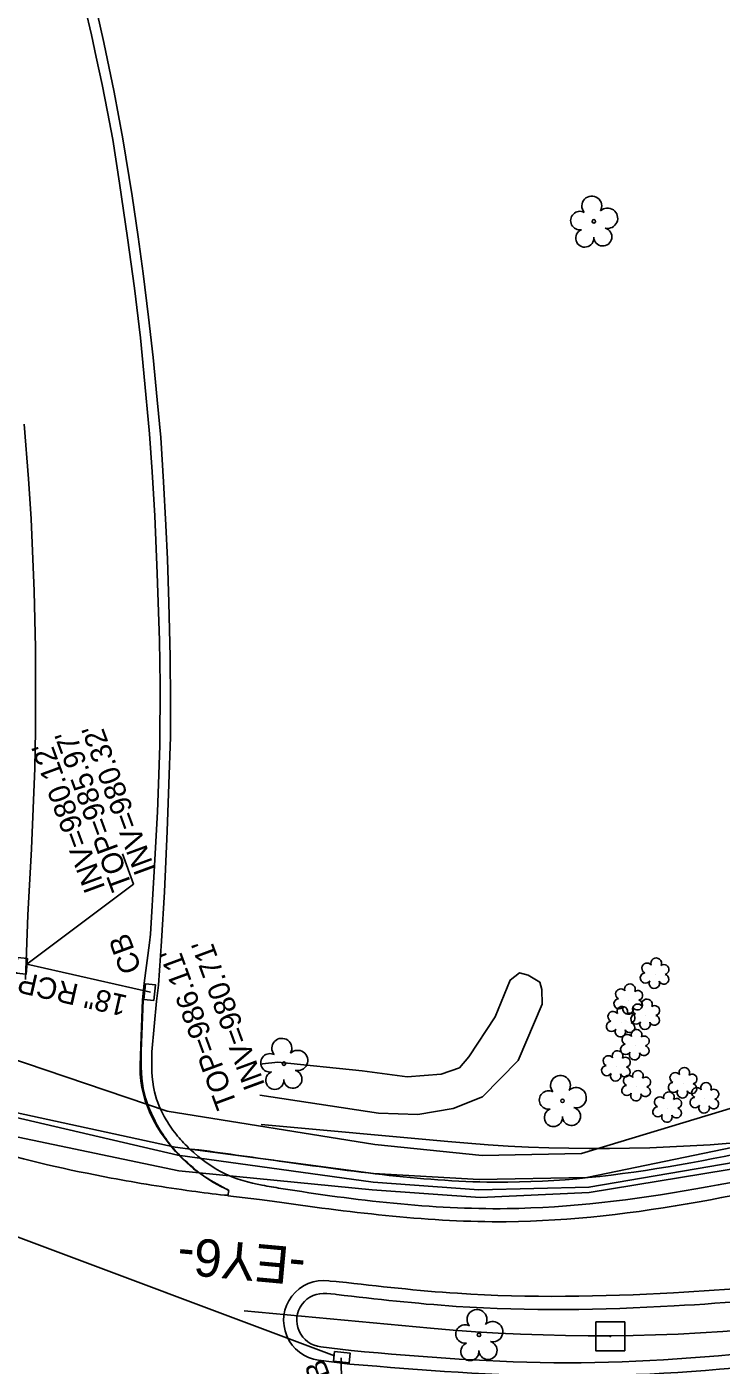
# Model space of a CAD drawing. Extents: x 1614427 to 1617186, y 896524 to 905462.
# Drawn here: x 1615875.6 to 1616005.3, y 904028.5 to 904278.6 of the extents above; entities that cross this region are included whole.
import ezdxf

# ---------------------------------------------------------------- set-up
doc = ezdxf.new("R2010")
doc.units = 0
for name, color, linetype in [('Exist Horizontal Alignment', 7, 'Continuous'), ('Exist Horizontal Alignment Direction Label', 7, 'Continuous'), ('Exist Right of Way Line', 7, 'Continuous'), ('Exist Roads Curbs', 7, 'Continuous'), ('Exist Roads EOP', 7, 'Continuous'), ('Exist Roads EOP Other', 7, 'Continuous'), ('Exist Roads EOT', 7, 'Continuous'), ('Exist Structure Minor Catch Basin', 7, 'Continuous'), ('Exist Structure Minor Catch Basin Leader', 7, 'Continuous'), ('Exist Structure Minor Catch Basin Text', 7, 'Continuous'), ('Exist Structure Minor Catch Basin Top Elevation', 7, 'Continuous'), ('Exist Structure Minor Pipes RCP 15 Inch', 7, 'Continuous'), ('Exist Structure Minor Pipes RCP 18 Inch', 7, 'Continuous'), ('Exist Structure Minor Pipes RCP 18 Inch Invert', 7, 'Continuous'), ('Exist Structure Minor Pipes RCP 18 Inch Text', 7, 'Continuous'), ('Exist Utilities Gas UG Line SUE LOS B', 7, 'Continuous'), ('Exist Utilities Other Pole With Base CELL', 7, 'Continuous'), ('Exist Utilities Power UG Cable SUE LOS B', 7, 'Continuous'), ('Exist Utilities Telephone UG FO SUE LOS B', 7, 'Continuous'), ('Exist Utilities Water UG Line SUE LOS B', 7, 'Continuous'), ('Exist Vegetation Hedge Row', 7, 'Continuous'), ('Exist Vegetation Shrub CELL', 7, 'Continuous'), ('Exist Vegetation Tree CELL', 7, 'Continuous')]:
    doc.layers.add(name, color=color, linetype=linetype)

msp = doc.modelspace()

# ---------------------------------------------------------------- linework, layer by layer
at = {"layer": 'Exist Horizontal Alignment'}
msp.add_line((1615916.17, 904038.64), (1615951, 904035.43), dxfattribs=at)
msp.add_arc((1615982.39, 904376.05), 342.06, 264.7333, 287.2667, dxfattribs=at)
at = {"layer": 'Exist Right of Way Line'}
msp.add_line((1615919.38, 904073.49), (1615954.21, 904070.28), dxfattribs=at)
msp.add_arc((1615982.39, 904376.05), 307.06, 264.7333, 287.2667, dxfattribs=at)
at = {"layer": 'Exist Roads Curbs'}
for p, q in [((1615898.96, 904087.08), (1615899.79, 904096.52)), ((1615933.17, 904041.78), (1615933.45, 904041.7)), ((1615936.16, 904031.22), (1615930.53, 904031.95))]:
    msp.add_line(p, q, dxfattribs=at)
for points in [[(1615893.5, 904257.65), (1615891.93, 904266.36), (1615889.96, 904275.68), (1615887.58, 904286.27), (1615885.87, 904293.7), (1615885.64, 904294.86), (1615885.5, 904296.02), (1615885.43, 904297.19), (1615885.44, 904298.37), (1615885.53, 904299.54), (1615885.57, 904299.9), (1615885.81, 904300.71), (1615886.13, 904301.49), (1615886.52, 904302.24), (1615886.98, 904302.96), (1615887.5, 904303.62), (1615887.72, 904303.86), (1615888.36, 904304.53), (1615889.06, 904305.14), (1615889.8, 904305.68), (1615890.59, 904306.16), (1615891.42, 904306.57), (1615892.28, 904306.9), (1615893.01, 904307.12)], [(1615899.79, 904096.52), (1615900.18, 904099.49), (1615900.77, 904107.74), (1615901.33, 904116.93), (1615901.83, 904128.29), (1615902.14, 904137.09), (1615902.4, 904145.94), (1615902.44, 904152.54), (1615902.38, 904160.85), (1615902.1, 904171.04), (1615901.84, 904179.09), (1615901.55, 904185.49), (1615901.14, 904193.58), (1615900.6, 904201.84), (1615899.96, 904208.86), (1615899.17, 904216.8), (1615898.31, 904224.32), (1615897.3, 904232.49), (1615896.4, 904239.36), (1615895.25, 904247.03), (1615893.5, 904257.65)], [(1615931.63, 904041.88), (1615932.4, 904041.81), (1615933.17, 904041.78)]]:
    msp.add_lwpolyline(points, dxfattribs=at)
msp.add_ellipse((1615930.99, 904036.92), major_axis=(-2.73, -4.18), ratio=0.999289, start_param=3.591477, end_param=6.769643, dxfattribs=at)
for points in [[(1616117.5, 904141.64), (1616119.61, 904131.89), (1616118.86, 904120.99), (1616117.54, 904115.53), (1616115.97, 904111.79), (1616113.21, 904107), (1616110.89, 904103.69), (1616104.9, 904097.71), (1616096.36, 904092.38), (1616065.87, 904079.76), (1616033.72, 904069.07), (1616000.54, 904061.43), (1615965.3, 904057.76), (1615923.02, 904061.54), (1615919.54, 904062.14), (1615912.5, 904064.32), (1615906.06, 904068.89), (1615903.75, 904071.29), (1615901.6, 904074.35), (1615899.43, 904079.59), (1615898.96, 904087.08)], [(1615933.45, 904041.7), (1615955.8, 904039.5), (1615996.5, 904039.58), (1616026.82, 904042.27), (1616053.3, 904046.56), (1616074.92, 904051.74), (1616097, 904058.32)], [(1616097.28, 904047.76), (1616058.24, 904037.32), (1616017.59, 904031.47), (1615976.53, 904028.93), (1615936.16, 904031.22)]]:
    msp.add_spline(points, degree=3, dxfattribs=at)
at = {"layer": 'Exist Roads EOP'}
for p, q in [((1615896.95, 904087.21), (1615897.3, 904096.73)), ((1615913.16, 904060.17), (1615913.33, 904061.16)), ((1615919.06, 904059.46), (1615913.16, 904060.17)), ((1615933.35, 904044.14), (1615933.92, 904044.1)), ((1615935.89, 904028.72), (1615930.08, 904029.44))]:
    msp.add_line(p, q, dxfattribs=at)
msp.add_lwpolyline([(1615931.99, 904044.27), (1615932.27, 904044.23), (1615933.35, 904044.14)], dxfattribs=at)
msp.add_ellipse((1615931.03, 904036.86), major_axis=(-4.43, -6.02), ratio=0.998974, start_param=3.648024, end_param=6.790921, dxfattribs=at)
for points in [[(1616119.62, 904142.34), (1616122.11, 904132.17), (1616121.32, 904120.53), (1616119.78, 904114.71), (1616118.22, 904110.85), (1616115.45, 904105.64), (1616112.79, 904102.18), (1616106.49, 904095.88), (1616097.4, 904090.23), (1616066.74, 904077.37), (1616034.38, 904066.74), (1616001.17, 904059.04), (1615965.14, 904055.31), (1615922.78, 904058.94), (1615919.06, 904059.46)], [(1615913.33, 904061.16), (1615908.86, 904063.71), (1615904.56, 904067.32), (1615902.11, 904070.03), (1615899.96, 904073.38), (1615897.55, 904079.2), (1615896.95, 904087.21)], [(1615933.92, 904044.1), (1615956.01, 904041.93), (1615996.4, 904042.04), (1616026.66, 904044.72), (1616052.83, 904049.09), (1616074.4, 904054.13), (1616095.78, 904060.53)], [(1616097.99, 904045.33), (1616058.52, 904034.87), (1616017.88, 904028.96), (1615976.43, 904026.45), (1615935.89, 904028.72)]]:
    msp.add_spline(points, degree=3, dxfattribs=at)
at = {"layer": 'Exist Roads EOP Other'}
msp.add_line((1615907.72, 904068.75), (1615906.28, 904068.84), dxfattribs=at)
for points in [[(1615891.63, 904257.51), (1615890.68, 904262.67), (1615889.66, 904267.81), (1615888.57, 904272.93), (1615887.64, 904277.08), (1615885.33, 904287.12)], [(1615913.18, 904061.27), (1615911.81, 904061.92), (1615910.48, 904062.64), (1615909.2, 904063.43), (1615907.95, 904064.29), (1615906.75, 904065.21), (1615906.68, 904065.27), (1615905.51, 904066.27), (1615904.4, 904067.33), (1615903.35, 904068.45), (1615902.35, 904069.62), (1615901.42, 904070.83), (1615900.71, 904071.86), (1615899.96, 904073.06), (1615899.27, 904074.29), (1615898.65, 904075.56), (1615898.1, 904076.86), (1615897.71, 904077.93), (1615897.36, 904079.14), (1615897.09, 904080.36), (1615896.89, 904081.61), (1615896.78, 904082.86), (1615896.74, 904084.11), (1615896.75, 904084.47), (1615896.92, 904089.91), (1615897.2, 904096.76), (1615897.48, 904099.9), (1615898.5, 904107.41), (1615898.67, 904109.06), (1615899.37, 904120.77), (1615900, 904131.92), (1615900.17, 904137.07), (1615900.43, 904144.27), (1615900.52, 904155.67), (1615900.38, 904163.91), (1615899.94, 904176.46), (1615899.48, 904187.22), (1615899.03, 904195.42), (1615898.52, 904202.52), (1615897.47, 904213.87), (1615896.81, 904220.44), (1615895.69, 904229.74), (1615894.41, 904239.18), (1615892.92, 904249.38), (1615891.63, 904257.51)], [(1615875.35, 904100.57), (1615875.75, 904112.62), (1615876.44, 904124.97), (1615877.08, 904140.06), (1615877.24, 904147.11), (1615877.21, 904162.52), (1615876.98, 904173.16), (1615876.39, 904186.64), (1615875.93, 904194.1), (1615875.09, 904204.35)]]:
    msp.add_lwpolyline(points, dxfattribs=at)
msp.add_spline([(1616106.96, 904106.8), (1616101.73, 904101.46), (1616094.3, 904096.91), (1616063.81, 904084.29), (1616032.43, 904073.94), (1615999.62, 904066.32), (1615965.45, 904062.7), (1615923.72, 904066.51), (1615907.72, 904068.75)], degree=3, dxfattribs=at)
at = {"layer": 'Exist Roads EOT'}
msp.add_line((1615912.51, 904060.26), (1615913.08, 904060.29), dxfattribs=at)
msp.add_ellipse((1615972.71, 904454.31), major_axis=(399.48, 187.91), ratio=0.997263, start_param=4.002237, end_param=4.130845, dxfattribs=at)
msp.add_spline([(1615844.2, 904077.02), (1615867.65, 904069.04), (1615891.35, 904063.48), (1615906.39, 904061.04), (1615912.51, 904060.26)], degree=3, dxfattribs=at)
at = {"layer": 'Exist Structure Minor Catch Basin'}
for points in [[(1615873.86, 904104.68), (1615875.71, 904104.51), (1615875.46, 904101.54), (1615873.67, 904101.75), (1615873.86, 904104.68)], [(1615899.3, 904096.67), (1615897.47, 904096.83), (1615897.76, 904099.79), (1615899.63, 904099.56), (1615899.3, 904096.67)], [(1615933.06, 904031.04), (1615932.86, 904029.28), (1615935.81, 904028.92), (1615936.01, 904030.72), (1615933.06, 904031.04)]]:
    msp.add_lwpolyline(points, dxfattribs=at)
at = {"layer": 'Exist Structure Minor Catch Basin Leader'}
for points in [[(1615875.61, 904103.46), (1615895.54, 904118.41), (1615893.47, 904124.04)], [(1615934.33, 904029.89), (1615934.75, 903996.19), (1615936.83, 903990.56)]]:
    msp.add_lwpolyline(points, dxfattribs=at)
at = {"layer": 'Exist Structure Minor Pipes RCP 15 Inch'}
msp.add_line((1615933.05, 904030.25), (1615731.82, 904105.72), dxfattribs=at)
msp.add_line((1615933.05, 904030.25), (1615731.82, 904105.72), dxfattribs=at)
at = {"layer": 'Exist Structure Minor Pipes RCP 18 Inch'}
msp.add_line((1615898.71, 904098.2), (1615875.61, 904103.46), dxfattribs=at)
msp.add_line((1615898.71, 904098.2), (1615875.61, 904103.46), dxfattribs=at)
at = {"layer": 'Exist Utilities Gas UG Line SUE LOS B'}
msp.add_lwpolyline([(1615854.58, 904082), (1615870.95, 904076.26), (1615903.3, 904069.25), (1615940.35, 904064.34), (1615960.08, 904063.22), (1615980.19, 904063.57), (1616009.39, 904069.59), (1616033.23, 904075.98), (1616065.79, 904088.71), (1616071.64, 904092.21), (1616080.09, 904108.75), (1616091.42, 904131.52), (1616096.21, 904140.27), (1616099.08, 904143.48), (1616102.9, 904146.03), (1616112.33, 904149.72)], dxfattribs=at)
at = {"layer": 'Exist Utilities Other Pole With Base CELL'}
msp.add_line((1615984.58, 904033.9), (1615984.58, 904033.9), dxfattribs=at)
msp.add_lwpolyline([(1615981.86, 904036.6), (1615987.26, 904036.6), (1615987.26, 904031.2), (1615981.86, 904031.2), (1615981.86, 904036.6)], dxfattribs=at)
msp.add_circle((1615984.58, 904033.9), 0.0707, dxfattribs=at)
at = {"layer": 'Exist Utilities Power UG Cable SUE LOS B'}
msp.add_lwpolyline([(1615850.39, 904094.27), (1615863.9, 904088.79), (1615901.78, 904075.97), (1615940.62, 904069.74), (1615960.64, 904067.69), (1615979.21, 904068.06), (1616007.56, 904076.64), (1616032.56, 904083.45), (1616059.29, 904090.87), (1616085.68, 904100.71), (1616093.61, 904105.52), (1616099.52, 904112.39), (1616102.28, 904129.68), (1616094.33, 904153), (1616085.98, 904178.59), (1616082.67, 904190.98), (1616081.58, 904203.76)], dxfattribs=at)
at = {"layer": 'Exist Utilities Telephone UG FO SUE LOS B'}
msp.add_lwpolyline([(1615856.34, 904076.83), (1615870.05, 904071.95), (1615904.01, 904064.8), (1615940.09, 904061.28), (1615960.29, 904059.81), (1615980.62, 904060.75), (1616010.57, 904065.68), (1616034.12, 904072.52), (1616066.45, 904085.29), (1616094.72, 904098.79), (1616101.16, 904102.54), (1616107.05, 904108.53), (1616109.46, 904114.97), (1616109.89, 904122.41), (1616109.17, 904135.16), (1616109.54, 904138.63), (1616110.42, 904139.78), (1616119.05, 904144.94), (1616144.14, 904158.05), (1616163.63, 904162.04), (1616171.06, 904164.3), (1616173.72, 904166.8)], dxfattribs=at)
at = {"layer": 'Exist Utilities Water UG Line SUE LOS B'}
msp.add_lwpolyline([(1615854.96, 904080.87), (1615870.68, 904075.46), (1615903.78, 904067.73), (1615940.26, 904062.7), (1615960.04, 904061.3), (1615980.56, 904061.76), (1616010.46, 904066.89), (1616033.97, 904071.93), (1616069.14, 904081.95), (1616099.73, 904091.26), (1616134.12, 904102.78), (1616151.27, 904109.12), (1616173.83, 904118)], dxfattribs=at)
at = {"layer": 'Exist Vegetation Hedge Row'}
for points in [[(1615938.23, 904083.52), (1615946.62, 904082.36), (1615953, 904082.91), (1615956.38, 904084.07), (1615958.13, 904086.09), (1615963.08, 904093.6), (1615965.84, 904100.45), (1615967.6, 904101.8), (1615969.21, 904101.4), (1615971.43, 904100.05), (1615971.79, 904098.68), (1615971.84, 904095.94), (1615967.35, 904085.46), (1615960.72, 904078.64), (1615955.21, 904076.48), (1615948.65, 904075.36), (1615941.25, 904075.57), (1615919.09, 904078.95)], [(1615919.48, 904084.71), (1615919.58, 904084.8), (1615922.48, 904085.14), (1615938.23, 904083.52)]]:
    msp.add_lwpolyline(points, dxfattribs=at)
at = {"layer": 'Exist Vegetation Shrub CELL'}
for p, q in [((1615992.92, 904101.56), (1615992.92, 904101.56)), ((1615988, 904096.73), (1615988, 904096.73)), ((1615986.58, 904092.51), (1615986.58, 904092.51)), ((1615991.17, 904093.89), (1615991.17, 904093.89)), ((1615989.24, 904088.21), (1615989.24, 904088.21)), ((1615985.7, 904084.24), (1615985.7, 904084.24)), ((1615989.48, 904080.54), (1615989.48, 904080.54)), ((1615998.16, 904081.1), (1615998.16, 904081.1)), ((1615995.27, 904076.55), (1615995.27, 904076.55)), ((1616002.21, 904078.27), (1616002.21, 904078.27))]:
    msp.add_line(p, q, dxfattribs=at)
for centre, radius, start, end in [((1615993.15, 904103.6), 0.99, 334.8391, 200.4717), ((1615991.12, 904100.85), 0.955, 95.1099, 327.9534), ((1615991.44, 904102.68), 0.968, 35.8908, 245.4216), ((1615994.56, 904100.63), 0.937, 204.9913, 73.4601), ((1615994.59, 904102.43), 0.929, 284.4567, 126.0861), ((1615988.23, 904098.77), 0.99, 334.8391, 200.4717), ((1615992.79, 904099.87), 0.984, 151.2797, 21.387), ((1615986.2, 904096.03), 0.955, 95.1099, 327.9534), ((1615986.52, 904097.86), 0.968, 35.8908, 245.4216), ((1615989.64, 904095.8), 0.937, 204.9913, 73.4601), ((1615989.68, 904097.6), 0.929, 284.4567, 126.0861), ((1615991.4, 904095.93), 0.99, 334.8391, 200.4717), ((1615985.1, 904093.64), 0.968, 35.8908, 245.4216), ((1615986.81, 904094.55), 0.99, 334.8391, 200.4717), ((1615987.88, 904095.05), 0.984, 151.2797, 21.387), ((1615988.25, 904093.38), 0.929, 284.4567, 126.0861), ((1615989.37, 904093.19), 0.955, 95.1099, 327.9534), ((1615989.69, 904095.02), 0.968, 35.8908, 245.4216), ((1615992.85, 904094.76), 0.929, 284.4567, 126.0861), ((1615984.78, 904091.81), 0.955, 95.1099, 327.9534), ((1615988.22, 904091.58), 0.937, 204.9913, 73.4601), ((1615991.05, 904092.21), 0.984, 151.2797, 21.387), ((1615992.81, 904092.96), 0.937, 204.9913, 73.4601), ((1615986.45, 904090.83), 0.984, 151.2797, 21.387), ((1615987.75, 904089.34), 0.968, 35.8908, 245.4216), ((1615989.47, 904090.25), 0.99, 334.8391, 200.4717), ((1615990.91, 904089.08), 0.929, 284.4567, 126.0861), ((1615985.93, 904086.28), 0.99, 334.8391, 200.4717), ((1615987.44, 904087.51), 0.955, 95.1099, 327.9534), ((1615989.11, 904086.53), 0.984, 151.2797, 21.387), ((1615990.87, 904087.29), 0.937, 204.9913, 73.4601), ((1615983.9, 904083.54), 0.955, 95.1099, 327.9534), ((1615984.22, 904085.37), 0.968, 35.8908, 245.4216), ((1615987.34, 904083.31), 0.937, 204.9913, 73.4601), ((1615987.37, 904085.11), 0.929, 284.4567, 126.0861), ((1615998.39, 904083.14), 0.99, 334.8391, 200.4717), ((1615985.57, 904082.56), 0.984, 151.2797, 21.387), ((1615988, 904081.67), 0.968, 35.8908, 245.4216), ((1615989.71, 904082.58), 0.99, 334.8391, 200.4717), ((1615991.16, 904081.41), 0.929, 284.4567, 126.0861), ((1615996.68, 904082.22), 0.968, 35.8908, 245.4216), ((1615999.83, 904081.97), 0.929, 284.4567, 126.0861), ((1615987.68, 904079.84), 0.955, 95.1099, 327.9534), ((1615989.35, 904078.86), 0.984, 151.2797, 21.387), ((1615991.12, 904079.61), 0.937, 204.9913, 73.4601), ((1615995.5, 904078.59), 0.99, 334.8391, 200.4717), ((1615996.36, 904080.39), 0.955, 95.1099, 327.9534), ((1615998.03, 904079.41), 0.984, 151.2797, 21.387), ((1615999.8, 904080.17), 0.937, 204.9913, 73.4601), ((1616000.73, 904079.4), 0.968, 35.8908, 245.4216), ((1616002.44, 904080.31), 0.99, 334.8391, 200.4717), ((1616003.89, 904079.14), 0.929, 284.4567, 126.0861), ((1615993.47, 904075.85), 0.955, 95.1099, 327.9534), ((1615993.79, 904077.68), 0.968, 35.8908, 245.4216), ((1615996.91, 904075.62), 0.937, 204.9913, 73.4601), ((1615996.94, 904077.42), 0.929, 284.4567, 126.0861), ((1616000.41, 904077.57), 0.955, 95.1099, 327.9534), ((1616002.09, 904076.59), 0.984, 151.2797, 21.387), ((1616003.85, 904077.34), 0.937, 204.9913, 73.4601), ((1615995.14, 904074.87), 0.984, 151.2797, 21.387)]:
    msp.add_arc(centre, radius, start, end, dxfattribs=at)
at = {"layer": 'Exist Vegetation Tree CELL'}
for p, q in [((1615981.5, 904242.23), (1615981.5, 904242.23)), ((1615923.61, 904084.85), (1615923.61, 904084.85)), ((1615975.64, 904077.89), (1615975.64, 904077.89)), ((1615960.05, 904034.17), (1615960.05, 904034.17))]:
    msp.add_line(p, q, dxfattribs=at)
for centre in [(1615981.5, 904242.23), (1615923.61, 904084.85), (1615975.64, 904077.89), (1615960.05, 904034.17)]:
    msp.add_circle(centre, 0.326, dxfattribs=at)
for centre, radius, start, end in [((1615981.11, 904245.1), 1.86, 330.1651, 219.7134), ((1615978.89, 904242.38), 1.73, 62.6636, 279.3457), ((1615984.05, 904242.81), 1.9, 257.1011, 134.1999), ((1615979.79, 904239.1), 1.69, 111.5671, 6.231), ((1615983.17, 904239.33), 1.7, 181.2822, 74.56), ((1615923.22, 904087.72), 1.86, 330.1651, 219.7134), ((1615921, 904085), 1.73, 62.6636, 279.3457), ((1615926.16, 904085.44), 1.9, 257.1011, 134.1999), ((1615921.9, 904081.73), 1.69, 111.5671, 6.231), ((1615925.28, 904081.95), 1.7, 181.2822, 74.56), ((1615975.26, 904080.77), 1.86, 330.1651, 219.7134), ((1615973.04, 904078.05), 1.73, 62.6636, 279.3457), ((1615978.19, 904078.48), 1.9, 257.1011, 134.1999), ((1615977.31, 904074.99), 1.7, 181.2822, 74.56), ((1615973.94, 904074.77), 1.69, 111.5671, 6.231), ((1615959.67, 904037.05), 1.86, 330.1651, 219.7134), ((1615962.6, 904034.76), 1.9, 257.1011, 134.1999), ((1615957.45, 904034.33), 1.73, 62.6636, 279.3457), ((1615958.35, 904031.05), 1.69, 111.5671, 6.231), ((1615961.72, 904031.27), 1.7, 181.2822, 74.56)]:
    msp.add_arc(centre, radius, start, end, dxfattribs=at)

# ---------------------------------------------------------------- texts
at = {"layer": 'Exist Horizontal Alignment Direction Label'}
msp.add_text('-EY6-', height=7, rotation=174.7333, dxfattribs=at).set_placement((1615927.89, 904050.33))
at = {"layer": 'Exist Structure Minor Catch Basin Text'}
for p in [(1615897.07, 904102.52), (1615933.62, 904022.95)]:
    msp.add_text('CB', height=4, rotation=110.2165, dxfattribs=at).set_placement(p)
at = {"layer": 'Exist Structure Minor Catch Basin Top Elevation'}
for s, p in [("TOP=985.97'", (1615895.32, 904118)), ("TOP=986.11'", (1615914.93, 904077.22))]:
    msp.add_text(s, height=4, rotation=110.2165, dxfattribs=at).set_placement(p)
at = {"layer": 'Exist Structure Minor Pipes RCP 18 Inch Invert'}
for s, p in [("INV=980.32'", (1615899.64, 904121.05)), ("INV=980.12'", (1615890.29, 904117.68)), ("INV=980.71'", (1615920.12, 904080.86))]:
    msp.add_text(s, height=4, rotation=110.2165, dxfattribs=at).set_placement(p)
at = {"layer": 'Exist Structure Minor Pipes RCP 18 Inch Text'}
msp.add_text('18" RCP', height=4, rotation=167.1839, dxfattribs=at).set_placement((1615894.58, 904097.52))

doc.saveas('drawing.dxf')
